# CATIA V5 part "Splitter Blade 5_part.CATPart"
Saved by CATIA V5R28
Part number: Splitter Blade 5_part
Definition: design
Nomenclature: Splitter Blade 5_part
Source: Unknown
Bounding box of the stored display mesh (mm): x -3.676 to 3.274, y 2.912 to 9.59, z 4.237 to 7.742
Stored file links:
  D:\paraturbo-cad\STEP\Turbocompressor_for_Christophe\Splitter Blade 5_part.CATPart
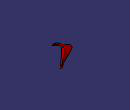
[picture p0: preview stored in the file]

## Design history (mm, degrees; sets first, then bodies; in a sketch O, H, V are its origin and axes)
Body1 "MANIFOLD_SOLID_BREP #69064" (main body)
  Solid1: solid without history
